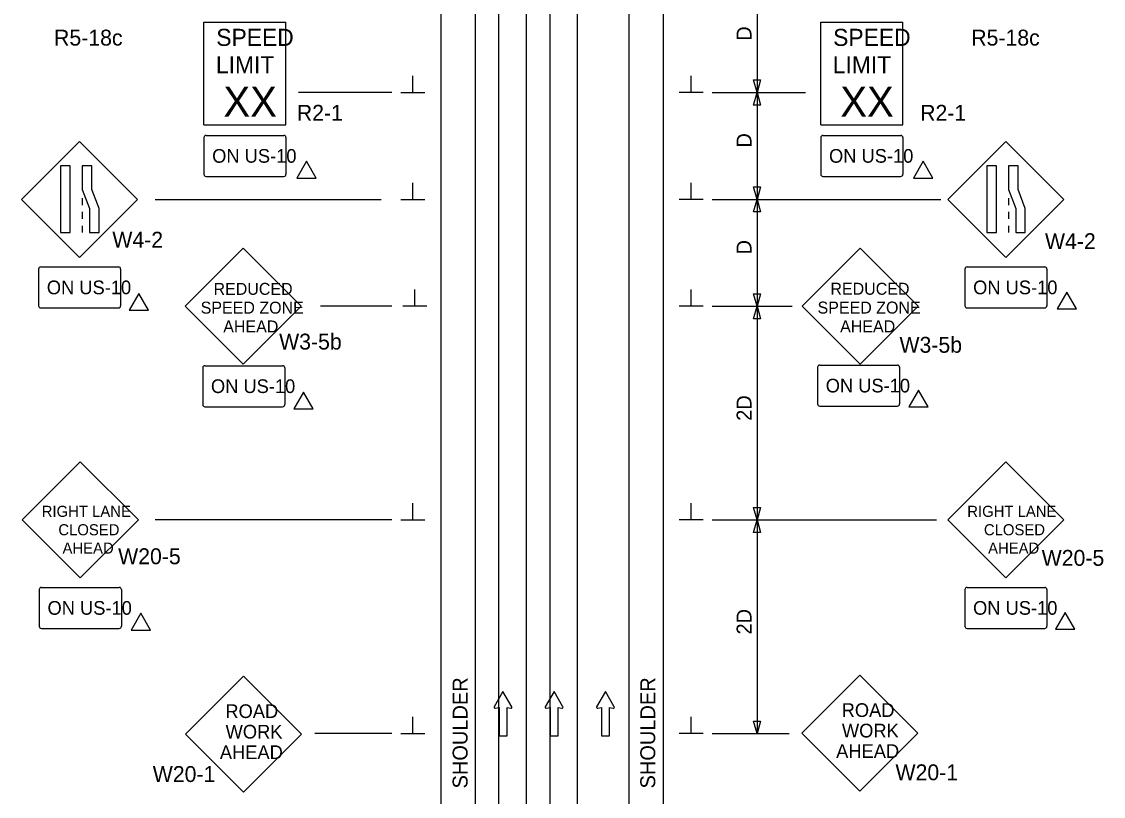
# Model space of a CAD drawing. Extents: x 16303 to 18479, y 5704 to 6974.
# Drawn here: x 16757 to 17264, y 6140 to 6502 of the extents above; entities that cross this region are included whole.
import ezdxf

# ---------------------------------------------------------------- set-up
doc = ezdxf.new("R2010")
doc.units = 0
for name, color, linetype in [('ALI_LEGAL_EX', 7, 'Continuous'), ('MT_SCRATCH_LEVEL_E', 7, 'Continuous'), ('PAVT_EDGE_EX', 7, 'Continuous'), ('TRAFFIC_SIGNS_PR', 7, 'Continuous'), ('TYPICAL_TEXT_DIMEN_PR', 7, 'Continuous')]:
    doc.layers.add(name, color=color, linetype=linetype)

msp = doc.modelspace()

# ---------------------------------------------------------------- linework, layer by layer
at = {"layer": 'ALI_LEGAL_EX'}
for p, q in [((16980.68, 6974.12), (16980.68, 6155.98)), ((17004.68, 6974.12), (17004.68, 6155.98)), ((16980.68, 6877.04), (16980.68, 6013.12)), ((17004.68, 6877.04), (17004.68, 6013.12)), ((16993.65, 6024.8), (16993.65, 6525.15)), ((17017.65, 6024.8), (17017.65, 6525.15))]:
    msp.add_line(p, q, dxfattribs=at)
for points in [[(16993.65, 6424.8), (16993.65, 6449.8)], [(17017.65, 6424.8), (17017.65, 6449.8)], [(16993.65, 6324.8), (16993.65, 6349.8)], [(17017.65, 6324.8), (17017.65, 6349.8)], [(16993.65, 6224.8), (16993.65, 6249.8)], [(17017.65, 6224.8), (17017.65, 6249.8)], [(16993.65, 6124.8), (16993.65, 6149.8)], [(17017.65, 6124.8), (17017.65, 6149.8)]]:
    msp.add_lwpolyline(points, dxfattribs=at)
at = {"layer": 'MT_SCRATCH_LEVEL_E'}
for p, q in [((16982.72, 6189.09), (16978.61, 6181.85)), ((16986.86, 6181.85), (16982.72, 6189.09)), ((17006.62, 6189.09), (17002.51, 6181.85)), ((17010.77, 6181.85), (17006.62, 6189.09)), ((17030.67, 6189.09), (17026.56, 6181.85)), ((17034.82, 6181.85), (17030.67, 6189.09)), ((16979.09, 6181.17), (16980.87, 6181.49)), ((16980.87, 6181.49), (16980.87, 6168.23)), ((16984.61, 6168.23), (16984.61, 6181.49)), ((16984.61, 6181.49), (16986.38, 6181.17)), ((17002.99, 6181.17), (17004.77, 6181.49)), ((17004.77, 6181.49), (17004.77, 6168.23)), ((17008.51, 6168.23), (17008.51, 6181.49)), ((17008.51, 6181.49), (17010.29, 6181.17)), ((17027.05, 6181.17), (17028.82, 6181.49)), ((17028.82, 6181.49), (17028.82, 6168.23)), ((17032.56, 6168.23), (17032.56, 6181.49)), ((17032.56, 6181.49), (17034.34, 6181.17)), ((16980.87, 6168.23), (16984.61, 6168.23)), ((17004.77, 6168.23), (17008.51, 6168.23)), ((17028.82, 6168.23), (17032.56, 6168.23))]:
    msp.add_line(p, q, dxfattribs=at)
for centre, start, end in [((16979.01, 6181.63), 150.4248, 279.9638), ((16986.45, 6181.63), 260.0362, 29.7731), ((17002.92, 6181.63), 150.4248, 279.9638), ((17010.36, 6181.63), 260.0362, 29.7731), ((17026.97, 6181.63), 150.4248, 279.9638), ((17034.41, 6181.63), 260.0362, 29.7731)]:
    msp.add_arc(centre, 0.463, start, end, dxfattribs=at)
at = {"layer": 'PAVT_EDGE_EX'}
for p, q in [((16953.65, 6525.15), (16953.65, 6062.71)), ((16969.65, 6525.15), (16969.65, 6062.71)), ((17041.65, 6525.15), (17041.65, 6062.71)), ((17057.65, 6525.15), (17057.65, 6062.71))]:
    msp.add_line(p, q, dxfattribs=at)
msp.add_arc((17357.65, 6475.15), 300, 180, 180.00000277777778, dxfattribs=at)
at = {"layer": 'TRAFFIC_SIGNS_PR'}
for p, q in [((16842.72, 6502.27), (16881.12, 6502.27)), ((16842.72, 6454.27), (16842.72, 6502.27)), ((16881.12, 6454.27), (16881.12, 6502.27)), ((17131.53, 6502.27), (17169.93, 6502.27)), ((17131.53, 6454.27), (17131.53, 6502.27)), ((17169.93, 6454.27), (17169.93, 6502.27)), ((16842.72, 6454.27), (16881.12, 6454.27)), ((17131.53, 6454.27), (17169.93, 6454.27)), ((16842.72, 6448.27), (16842.72, 6431.07)), ((16843.72, 6449.27), (16880.12, 6449.27)), ((16881.12, 6448.27), (16881.12, 6431.07)), ((17131.53, 6448.27), (17131.53, 6431.07)), ((17132.53, 6449.27), (17168.93, 6449.27)), ((17169.93, 6448.27), (17169.93, 6431.07)), ((16784.5, 6446.48), (16757.35, 6419.33)), ((16811.65, 6419.33), (16784.5, 6446.48)), ((17218.2, 6446.48), (17191.05, 6419.33)), ((17245.35, 6419.33), (17218.2, 6446.48)), ((16843.72, 6430.07), (16880.12, 6430.07)), ((17132.53, 6430.07), (17168.93, 6430.07)), ((16757.35, 6419.33), (16784.5, 6392.17)), ((16784.5, 6392.17), (16811.65, 6419.33)), ((16785.74, 6419.82), (16785.74, 6416.62)), ((17191.05, 6419.33), (17218.2, 6392.17)), ((17218.2, 6392.17), (17245.35, 6419.33)), ((17219.44, 6419.82), (17219.44, 6416.62)), ((16785.74, 6413.42), (16785.74, 6410.22)), ((17219.44, 6413.42), (17219.44, 6410.22)), ((16785.74, 6407.02), (16785.74, 6403.82)), ((17219.44, 6407.02), (17219.44, 6403.82)), ((16861.13, 6396.49), (16833.98, 6369.34)), ((16888.29, 6369.34), (16861.13, 6396.49)), ((17149.95, 6396.53), (17122.8, 6369.38)), ((17177.11, 6369.38), (17149.95, 6396.53)), ((16765.3, 6386.73), (16765.3, 6369.53)), ((16766.3, 6387.73), (16802.7, 6387.73)), ((16803.7, 6386.73), (16803.7, 6369.53)), ((17199, 6386.73), (17199, 6369.53)), ((17200, 6387.73), (17236.4, 6387.73)), ((17237.4, 6386.73), (17237.4, 6369.53)), ((16766.3, 6368.53), (16802.7, 6368.53)), ((16833.98, 6369.34), (16861.13, 6342.19)), ((16861.13, 6342.19), (16888.29, 6369.34)), ((17122.8, 6369.38), (17149.95, 6342.23)), ((17149.95, 6342.23), (17177.11, 6369.38)), ((17200, 6368.53), (17236.4, 6368.53)), ((16843.14, 6341.49), (16879.54, 6341.49)), ((17130.99, 6341.77), (17167.39, 6341.77)), ((16842.14, 6340.49), (16842.14, 6323.29)), ((16880.54, 6340.49), (16880.54, 6323.29)), ((17129.99, 6340.77), (17129.99, 6323.57)), ((17168.39, 6340.77), (17168.39, 6323.57)), ((16843.14, 6322.29), (16879.54, 6322.29)), ((17130.99, 6322.57), (17167.39, 6322.57)), ((16784.83, 6296.49), (16757.67, 6269.33)), ((16811.99, 6269.33), (16784.83, 6296.49)), ((17218.18, 6296.49), (17191.02, 6269.33)), ((17245.34, 6269.33), (17218.18, 6296.49)), ((16757.67, 6269.33), (16784.83, 6242.17)), ((16784.83, 6242.17), (16811.99, 6269.33)), ((17191.02, 6269.33), (17218.18, 6242.17)), ((17218.18, 6242.17), (17245.34, 6269.33)), ((16765.63, 6236.73), (16765.63, 6219.53)), ((16766.63, 6237.73), (16803.03, 6237.73)), ((16804.03, 6236.73), (16804.03, 6219.53)), ((17198.98, 6236.73), (17198.98, 6219.53)), ((17199.98, 6237.73), (17236.38, 6237.73)), ((17237.38, 6236.73), (17237.38, 6219.53)), ((16766.63, 6218.53), (16803.03, 6218.53)), ((17199.98, 6218.53), (17236.38, 6218.53)), ((16861.19, 6196.23), (16834.04, 6169.07)), ((16888.35, 6169.07), (16861.19, 6196.23)), ((17149.75, 6196.73), (17122.59, 6169.58)), ((17176.9, 6169.58), (17149.75, 6196.73)), ((16834.04, 6169.07), (16861.19, 6141.91)), ((16861.19, 6141.91), (16888.35, 6169.07)), ((17122.59, 6169.58), (17149.75, 6142.42)), ((17149.75, 6142.42), (17176.9, 6169.58))]:
    msp.add_line(p, q, dxfattribs=at)
for points in [[(16775.61, 6435.06), (16775.61, 6403.82), (16780.1, 6403.82), (16780.1, 6435.06)], [(16785.74, 6435.06), (16785.74, 6423.88), (16789.09, 6415), (16789.09, 6403.82), (16793.58, 6403.82), (16793.58, 6415), (16790.23, 6423.88), (16790.23, 6435.06)], [(17209.3, 6435.06), (17209.3, 6403.82), (17213.8, 6403.82), (17213.8, 6435.06)], [(17219.44, 6435.06), (17219.44, 6423.88), (17222.78, 6415), (17222.78, 6403.82), (17227.28, 6403.82), (17227.28, 6415), (17223.93, 6423.88), (17223.93, 6435.06)]]:
    msp.add_lwpolyline(points, close=True, dxfattribs=at)
for centre, start, end in [((16843.72, 6448.27), 90, 180), ((16880.12, 6448.27), 0, 90), ((17132.53, 6448.27), 90, 180), ((17168.93, 6448.27), 0, 90), ((16843.72, 6431.07), 180, 270), ((16880.12, 6431.07), 270, 0), ((17132.53, 6431.07), 180, 270), ((17168.93, 6431.07), 270, 0), ((16766.3, 6386.73), 90, 180), ((16802.7, 6386.73), 0, 90), ((17200, 6386.73), 90, 180), ((17236.4, 6386.73), 0, 90), ((16766.3, 6369.53), 180, 270), ((16802.7, 6369.53), 270, 0), ((17200, 6369.53), 180, 270), ((17236.4, 6369.53), 270, 0), ((16843.14, 6340.49), 90, 180), ((16879.54, 6340.49), 0, 90), ((17130.99, 6340.77), 90, 180), ((17167.39, 6340.77), 0, 90), ((16843.14, 6323.29), 180, 270), ((16879.54, 6323.29), 270, 0), ((17130.99, 6323.57), 180, 270), ((17167.39, 6323.57), 270, 0), ((16766.63, 6236.73), 90, 180), ((16803.03, 6236.73), 0, 90), ((17199.98, 6236.73), 90, 180), ((17236.38, 6236.73), 0, 90), ((16766.63, 6219.53), 180, 270), ((16803.03, 6219.53), 270, 0), ((17199.98, 6219.53), 180, 270), ((17236.38, 6219.53), 270, 0)]:
    msp.add_arc(centre, 1, start, end, dxfattribs=at)
at = {"layer": 'TYPICAL_TEXT_DIMEN_PR'}
for p, q in [((17101.65, 6519.33), (17101.65, 6469.33)), ((16940.52, 6469.33), (16940.52, 6477.11)), ((17070.77, 6469.33), (17070.77, 6477.11)), ((17101.65, 6469.33), (17100.08, 6475.19)), ((17100.08, 6475.19), (17101.65, 6475.19)), ((17101.65, 6475.19), (17103.22, 6475.19)), ((17103.22, 6475.19), (17101.65, 6469.33)), ((16930.65, 6469.33), (16886.93, 6469.33)), ((16934.9, 6469.33), (16946.15, 6469.33)), ((17076.4, 6469.33), (17065.15, 6469.33)), ((17080.65, 6469.33), (17124.34, 6469.33)), ((17100.08, 6463.47), (17101.65, 6469.33)), ((17101.65, 6469.33), (17101.65, 6419.33)), ((17101.65, 6469.33), (17103.22, 6463.47)), ((17101.65, 6463.47), (17100.08, 6463.47)), ((17103.22, 6463.47), (17101.65, 6463.47)), ((16940.52, 6419.33), (16940.52, 6427.11)), ((17070.77, 6419.33), (17070.77, 6427.11)), ((17101.65, 6419.33), (17100.08, 6425.19)), ((17100.08, 6425.19), (17101.65, 6425.19)), ((17101.65, 6425.19), (17103.22, 6425.19)), ((17103.22, 6425.19), (17101.65, 6419.33)), ((16819.87, 6419.33), (16925.67, 6419.33)), ((16934.9, 6419.33), (16946.15, 6419.33)), ((17076.4, 6419.33), (17065.15, 6419.33)), ((17080.65, 6419.33), (17187.78, 6419.33)), ((17100.08, 6413.47), (17101.65, 6419.33)), ((17101.65, 6419.33), (17101.65, 6369.33)), ((17101.65, 6419.33), (17103.22, 6413.47)), ((17101.65, 6413.47), (17100.08, 6413.47)), ((17103.22, 6413.47), (17101.65, 6413.47)), ((16941.49, 6369.33), (16941.49, 6377.11)), ((17070.77, 6369.33), (17070.77, 6377.11)), ((17101.65, 6369.33), (17100.08, 6375.19)), ((17100.08, 6375.19), (17101.65, 6375.19)), ((17101.65, 6375.19), (17103.22, 6375.19)), ((17103.22, 6375.19), (17101.65, 6369.33)), ((16930.65, 6369.33), (16897.2, 6369.33)), ((16947.11, 6369.33), (16935.86, 6369.33)), ((17076.4, 6369.33), (17065.15, 6369.33)), ((17080.65, 6369.33), (17118.07, 6369.33)), ((17100.08, 6363.47), (17101.65, 6369.33)), ((17101.65, 6369.33), (17101.65, 6269.33)), ((17101.65, 6369.33), (17103.22, 6363.47)), ((17101.65, 6363.47), (17100.08, 6363.47)), ((17103.22, 6363.47), (17101.65, 6363.47)), ((16940.52, 6269.33), (16940.52, 6277.11)), ((17070.77, 6269.33), (17070.77, 6277.11)), ((17101.65, 6269.33), (17100.08, 6275.19)), ((17100.08, 6275.19), (17101.65, 6275.19)), ((17101.65, 6275.19), (17103.22, 6275.19)), ((17103.22, 6275.19), (17101.65, 6269.33)), ((16930.65, 6269.33), (16819.87, 6269.33)), ((16934.9, 6269.33), (16946.15, 6269.33)), ((17076.4, 6269.33), (17065.15, 6269.33)), ((17080.65, 6269.33), (17185.68, 6269.33)), ((17100.08, 6263.47), (17101.65, 6269.33)), ((17101.65, 6269.33), (17101.65, 6169.33)), ((17101.65, 6269.33), (17103.22, 6263.47)), ((17101.65, 6263.47), (17100.08, 6263.47)), ((17103.22, 6263.47), (17101.65, 6263.47)), ((16940.52, 6169.33), (16940.52, 6177.11)), ((17070.77, 6169.33), (17070.77, 6177.11)), ((17101.65, 6169.33), (17100.08, 6175.19)), ((17100.08, 6175.19), (17101.65, 6175.19)), ((17101.65, 6175.19), (17103.22, 6175.19)), ((17103.22, 6175.19), (17101.65, 6169.33)), ((16930.65, 6169.33), (16894.65, 6169.33)), ((16934.9, 6169.33), (16946.15, 6169.33)), ((17076.4, 6169.33), (17065.15, 6169.33)), ((17080.65, 6169.33), (17116.65, 6169.33))]:
    msp.add_line(p, q, dxfattribs=at)
for points in [[(16890.67, 6437.14), (16886.14, 6429.3), (16895.19, 6429.3)], [(17179.48, 6437.14), (17174.96, 6429.3), (17184.01, 6429.3)], [(16812.19, 6375.32), (16807.67, 6367.48), (16816.72, 6367.48)], [(17246.7, 6375.91), (17242.18, 6368.07), (17251.23, 6368.07)], [(16889.36, 6329.08), (16884.83, 6321.24), (16893.88, 6321.24)], [(17177.19, 6330.02), (17172.67, 6322.19), (17181.72, 6322.19)], [(16813.08, 6225.62), (16808.56, 6217.79), (16817.61, 6217.79)], [(17245.98, 6225.99), (17241.45, 6218.15), (17250.51, 6218.15)]]:
    msp.add_lwpolyline(points, close=True, dxfattribs=at)

# ---------------------------------------------------------------- texts
at = {"layer": 'TRAFFIC_SIGNS_PR'}
for s, height, p in [('R5-18c', 7.44, (16772.53, 6491.29)), ('SPEED', 8, (16848.48, 6491.14)), ('SPEED', 8, (17137.3, 6491.14)), ('R5-18c', 7.44, (17201.96, 6491.29)), ('LIMIT', 8, (16848.32, 6478.34)), ('LIMIT', 8, (17137.14, 6478.34)), ('XX', 14.031, (16851.83, 6458.03)), ('XX', 14.031, (17140.65, 6458.03)), ('R2-1', 7.44, (16886.19, 6456.12)), ('R2-1', 7.44, (17178.03, 6456.12)), ('ON US-10', 6.4, (16846.56, 6436.47)), ('ON US-10', 6.4, (17135.37, 6436.47)), ('W4-2', 7.44, (16799.81, 6396.74)), ('W4-2', 7.441, (17236.48, 6396.03)), ('ON US-10', 6.401, (16769.14, 6374.93)), ('REDUCED', 5.6, (16847.19, 6374.65)), ('REDUCED', 5.6, (17136.01, 6374.69)), ('ON US-10', 6.401, (17202.84, 6374.93)), ('SPEED ZONE', 5.6, (16841.18, 6365.85)), ('SPEED ZONE', 5.6, (17130, 6365.89)), ('AHEAD', 5.6, (16851.74, 6357.05)), ('AHEAD', 5.6, (17140.56, 6357.09)), ('W3-5b', 7.44, (16877.9, 6349.04)), ('W3-5b', 7.44, (17168.35, 6347.55)), ('ON US-10', 6.4, (16845.98, 6328.7)), ('ON US-10', 6.4, (17133.83, 6328.97)), ('RIGHT LANE', 5.201, (16766.75, 6270.73)), ('RIGHT LANE', 5.201, (17200.1, 6270.73)), ('CLOSED', 5.201, (16774.54, 6262.12)), ('CLOSED', 5.201, (17207.89, 6262.12)), ('AHEAD', 5.201, (16776.49, 6253.52)), ('W20-5', 7.441, (16802.53, 6248.58)), ('AHEAD', 5.201, (17209.84, 6253.52)), ('W20-5', 7.441, (17234.93, 6247.83)), ('ON US-10', 6.401, (16769.47, 6224.93)), ('ON US-10', 6.401, (17202.82, 6224.93)), ('ROAD', 6.401, (16852.73, 6176.61)), ('ROAD', 6.401, (17141.29, 6177.11)), ('WORK', 6.401, (17141.4, 6167.51)), ('WORK', 6.401, (16852.84, 6167.01)), ('AHEAD', 6.401, (16850.15, 6157.4)), ('AHEAD', 6.401, (17138.71, 6157.91)), ('W20-1', 7.441, (16818.73, 6146.67)), ('W20-1', 7.441, (17166.49, 6147.47))]:
    msp.add_text(s, height=height, dxfattribs=at).set_placement(p)
at = {"layer": 'TYPICAL_TEXT_DIMEN_PR'}
for s, p in [('D', (17099.09, 6493.55)), ('D', (17099.09, 6443.55)), ('D', (17099.09, 6393.55)), ('2D', (17099.09, 6315.69)), ('2D', (17099.09, 6215.69)), ('SHOULDER', (16966.14, 6143.64)), ('SHOULDER', (17054, 6143.64))]:
    msp.add_text(s, height=7, rotation=90, dxfattribs=at).set_placement(p)

doc.saveas('drawing.dxf')
